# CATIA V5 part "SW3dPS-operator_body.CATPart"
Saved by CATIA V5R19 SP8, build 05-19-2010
Part number: SW3dPS-operator_body
Revision: ANY
Definition: SW3dPS-operator_body
Source: Unknown
Bounding box of the stored display mesh (mm): x -232.41 to 232.41, y -562.422 to 85.537, z -111.125 to 111.125
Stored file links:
  G:\EU_thinkMotion\CFAO_2010\MMS_groupe1\MMS_groupe1\OK\rragonneau\rragonneau\SW3dPS-operator_body.CATPart
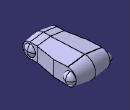
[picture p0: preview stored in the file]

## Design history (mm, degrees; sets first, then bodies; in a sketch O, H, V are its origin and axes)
Body1 "NONE" (main body)
  Solid1 "Manifold Solid #15337": solid without history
